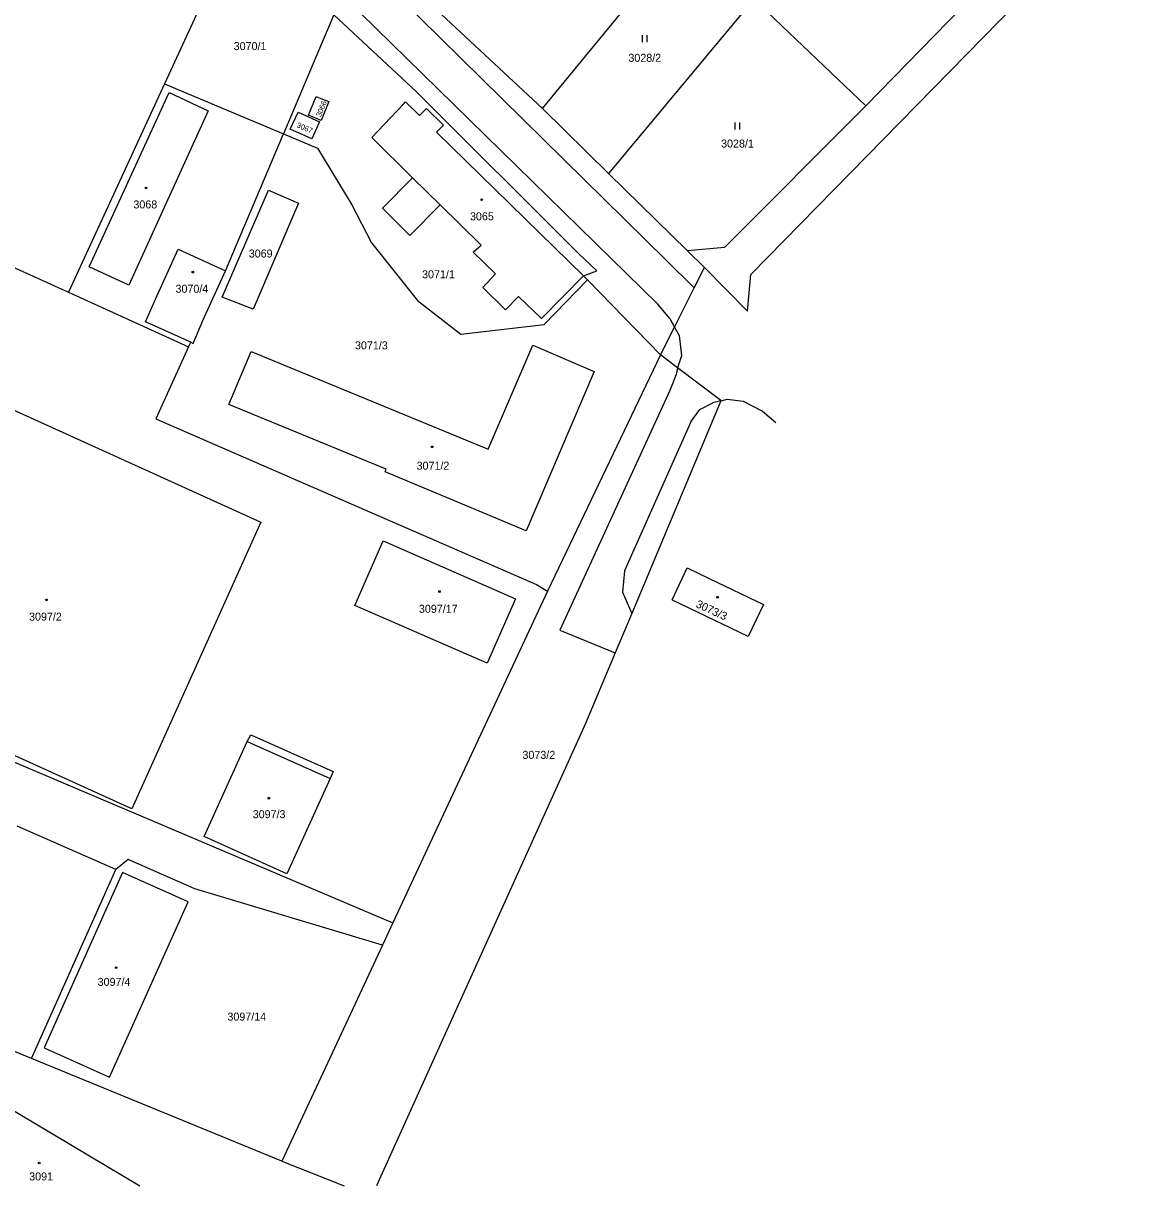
# Model space of a CAD drawing. Extents: x -527335 to -526256, y -1079142 to -1077809.
# Drawn here: x -526618.3 to -526379.4, y -1079141.5 to -1078894.6 of the extents above; entities that cross this region are included whole.
import ezdxf

# ---------------------------------------------------------------- set-up
doc = ezdxf.new("R2010")
doc.units = 0
for name, color, linetype in [('Vrstva 1', 7, 'Continuous'), ('Vrstva 2', 7, 'Continuous'), ('Vrstva 3', 7, 'Continuous'), ('Vrstva 4', 7, 'Continuous'), ('Vrstva 5', 7, 'Continuous')]:
    doc.layers.add(name, color=color, linetype=linetype)

msp = doc.modelspace()

# ---------------------------------------------------------------- linework, layer by layer
at = {"layer": 'Vrstva 1'}
for p, q in [((-526508.07, -1078912.73), (-526477.68, -1078875.63)), ((-526463.23, -1078889.43), (-526494.04, -1078926.52)), ((-526463.23, -1078889.43), (-526439.43, -1078912.18)), ((-526552.41, -1078892.82), (-526555.43, -1078899.96)), ((-526534.91, -1078909.1), (-526552.41, -1078892.82)), ((-526529.63, -1078892.67), (-526508.07, -1078912.73)), ((-526555.43, -1078899.96), (-526563.09, -1078918.07)), ((-526588.32, -1078907.48), (-526608.69, -1078951.75)), ((-526588.32, -1078907.48), (-526563.09, -1078918.07)), ((-526494.04, -1078926.52), (-526508.07, -1078912.73)), ((-526575.39, -1078947.17), (-526563.09, -1078918.07)), ((-526563.09, -1078918.07), (-526555.83, -1078921.12)), ((-526477.29, -1078942.98), (-526494.04, -1078926.52)), ((-526477.29, -1078942.98), (-526473.72, -1078946.48)), ((-526473.72, -1078946.48), (-526464.58, -1078955.73)), ((-526483.04, -1078965.07), (-526498.52, -1078949.13)), ((-526608.69, -1078951.75), (-526583.25, -1078963.33)), ((-526483.04, -1078965.07), (-526507.04, -1079015.24)), ((-526479.44, -1078967.79), (-526483.04, -1078965.07)), ((-526470.21, -1078974.76), (-526479.44, -1078967.79)), ((-526470.15, -1078974.81), (-526470.21, -1078974.76)), ((-526507.04, -1079015.24), (-526539.87, -1079085.69)), ((-526498.95, -1079043.36), (-526542.74, -1079140.28)), ((-526598.64, -1079074.35), (-526619.63, -1079065.16)), ((-526616.56, -1079114.53), (-526598.64, -1079074.35)), ((-526539.87, -1079085.69), (-526542.07, -1079090.41)), ((-526542.07, -1079090.41), (-526563.45, -1079136.3)), ((-526616.56, -1079114.53), (-526662.29, -1079095.78)), ((-526563.45, -1079136.3), (-526616.56, -1079114.53)), ((-526563.45, -1079136.3), (-526550.17, -1079141.53)), ((-526542.74, -1079140.28), (-526543.31, -1079141.53))]:
    msp.add_line(p, q, dxfattribs=at)
for points in [[(-526410.53, -1078846.68), (-526397.22, -1078864.18), (-526401.55, -1078873.2), (-526439.43, -1078912.18)], [(-526464.58, -1078955.73), (-526463.83, -1078947.95), (-526379.39, -1078861.67)], [(-526572.83, -1078873.83), (-526575.65, -1078879.95), (-526588.32, -1078907.48)], [(-526579.03, -1078913.2), (-526595.91, -1078950.25), (-526604.31, -1078946.38), (-526587.37, -1078909.35), (-526579.03, -1078913.2)], [(-526554.76, -1078910.7), (-526553.45, -1078911.2), (-526555.06, -1078915.25), (-526557.74, -1078914.16), (-526556.12, -1078910.18), (-526554.76, -1078910.7)], [(-526499.36, -1078948.26), (-526508.33, -1078957.3), (-526513.2, -1078952.65), (-526515.92, -1078955.46), (-526520.73, -1078950.74), (-526518.09, -1078947.84), (-526522.83, -1078943.22), (-526521.14, -1078941.78), (-526529.82, -1078933.2), (-526536.22, -1078939.7), (-526542.04, -1078933.91), (-526535.66, -1078927.43), (-526544.35, -1078918.84), (-526537.68, -1078911.85), (-526537.18, -1078911.32), (-526534.21, -1078914.22), (-526532.69, -1078912.68), (-526529.11, -1078916.24), (-526530.6, -1078917.74), (-526499.36, -1078948.26)], [(-526498.52, -1078949.13), (-526499.36, -1078948.26), (-526496.56, -1078947.22), (-526500.39, -1078943.58), (-526534.91, -1078909.1)], [(-526561.68, -1078917.14), (-526559.96, -1078913.52), (-526555.39, -1078915.52), (-526557.04, -1078919.16), (-526561.68, -1078917.14)], [(-526439.43, -1078912.18), (-526469.48, -1078942.24), (-526477.29, -1078942.98)], [(-526691.64, -1078914.07), (-526638.3, -1078938.3), (-526619.95, -1078946.64), (-526608.69, -1078951.75)], [(-526555.83, -1078921.12), (-526548.53, -1078933.15), (-526544.38, -1078941.22), (-526534.65, -1078953.51), (-526525.41, -1078960.63), (-526507.76, -1078958.6), (-526498.52, -1078949.13)], [(-526566.28, -1078930.06), (-526559.91, -1078932.85), (-526569.53, -1078955.32), (-526576.11, -1078952.82), (-526566.28, -1078930.06)], [(-526583.25, -1078963.33), (-526582.73, -1078962.38), (-526582.25, -1078962.6), (-526580.18, -1078957.77), (-526575.39, -1078947.17)], [(-526483.04, -1078965.07), (-526480.07, -1078959.14), (-526475.9, -1078950.84), (-526473.72, -1078946.48)], [(-526583.25, -1078963.33), (-526590.15, -1078978.64), (-526509.33, -1079013.84), (-526507.04, -1079015.24)], [(-526541.48, -1078989.9), (-526541.24, -1078989.35), (-526574.66, -1078975.58), (-526569.94, -1078964.3), (-526519.59, -1078985.06), (-526510.15, -1078962.99), (-526497.11, -1078968.56), (-526511.58, -1079002.41), (-526541.48, -1078989.9)], [(-526595.23, -1079061.45), (-526657.34, -1079033.27), (-526629.87, -1078972.47), (-526567.85, -1079000.59), (-526595.23, -1079061.45)], [(-526470.21, -1078974.76), (-526470.24, -1078974.84), (-526489.15, -1079019.96), (-526492.67, -1079028.37), (-526498.95, -1079043.36)], [(-526792.35, -1078978.47), (-526658.25, -1079035.42), (-526539.87, -1079085.69)], [(-526519.83, -1079030.53), (-526547.95, -1079018.26), (-526541.93, -1079004.57), (-526513.85, -1079016.84), (-526519.83, -1079030.53)], [(-526461.14, -1079018.05), (-526464.39, -1079024.87), (-526480.51, -1079017.14), (-526480.59, -1079017.1), (-526477.34, -1079010.26), (-526472.67, -1079012.56), (-526461.14, -1079018.05)], [(-526553.19, -1079055.06), (-526562.38, -1079075.31), (-526579.89, -1079067.37), (-526570.75, -1079047.18), (-526570.02, -1079045.72), (-526552.49, -1079053.53), (-526553.19, -1079055.06)], [(-526542.07, -1079090.41), (-526581.9, -1079078.47), (-526596.06, -1079072.23), (-526598.64, -1079074.35)], [(-526599.97, -1079118.46), (-526583.3, -1079081.2), (-526597.22, -1079074.98), (-526613.89, -1079112.23), (-526599.97, -1079118.46)], [(-526661.2, -1079101.27), (-526659.92, -1079099.09), (-526639.61, -1079110.66), (-526641.13, -1079113.22), (-526593.58, -1079141.53)]]:
    msp.add_lwpolyline(points, dxfattribs=at)
at = {"layer": 'Vrstva 3'}
for p, q in [((-526486.87, -1078898.63), (-526486.87, -1078897.13)), ((-526485.87, -1078898.63), (-526485.87, -1078897.13)), ((-526467.19, -1078917.21), (-526467.19, -1078915.71)), ((-526466.19, -1078917.21), (-526466.19, -1078915.71))]:
    msp.add_line(p, q, dxfattribs=at)
at = {"layer": 'Vrstva 4'}
for p, q in [((-526483.62, -1078954.28), (-526598.1, -1078842.1)), ((-526481.85, -1078944.96), (-526565.2, -1078862.78)), ((-526535.66, -1078927.43), (-526529.82, -1078933.2)), ((-526590.22, -1078953.19), (-526585.42, -1078942.57)), ((-526585.42, -1078942.57), (-526575.39, -1078947.17)), ((-526481.85, -1078944.96), (-526475.9, -1078950.84)), ((-526592.39, -1078958), (-526590.22, -1078953.19)), ((-526481.04, -1078957.33), (-526483.62, -1078954.28)), ((-526582.73, -1078962.38), (-526592.39, -1078958)), ((-526481.04, -1078957.33), (-526480.07, -1078959.14)), ((-526480.07, -1078959.14), (-526479.1, -1078960.94)), ((-526479.1, -1078960.94), (-526478.59, -1078965.24)), ((-526478.59, -1078965.24), (-526479.44, -1078967.79)), ((-526479.44, -1078967.79), (-526479.72, -1078969.22)), ((-526479.72, -1078969.22), (-526481.04, -1078972.63)), ((-526481.04, -1078972.63), (-526504.43, -1079023.55)), ((-526474.7, -1078976.67), (-526471.9, -1078975.25)), ((-526470.24, -1078974.84), (-526471.9, -1078975.25)), ((-526470.15, -1078974.81), (-526470.24, -1078974.84)), ((-526470.15, -1078974.81), (-526468.86, -1078974.49)), ((-526468.86, -1078974.49), (-526465.47, -1078974.88)), ((-526465.47, -1078974.88), (-526461.4, -1078977.04)), ((-526476.58, -1078979.26), (-526474.7, -1078976.67)), ((-526461.4, -1078977.04), (-526458.54, -1078979.43)), ((-526476.58, -1078979.26), (-526490.66, -1079010.95)), ((-526490.66, -1079010.95), (-526491.09, -1079015.48)), ((-526491.09, -1079015.48), (-526489.15, -1079019.96)), ((-526504.43, -1079023.55), (-526492.67, -1079028.37)), ((-526570.75, -1079047.18), (-526553.19, -1079055.06))]:
    msp.add_line(p, q, dxfattribs=at)
at = {"layer": 'Vrstva 5'}
for centre in [(-526592.26, -1078929.6), (-526521.01, -1078932.08), (-526582.32, -1078947.47), (-526531.49, -1078984.58), (-526529.95, -1079015.32), (-526613.39, -1079017.08), (-526470.94, -1079016.53), (-526566.18, -1079059.21), (-526598.59, -1079095.22), (-526614.92, -1079136.71)]:
    msp.add_circle(centre, 0.175, dxfattribs=at)

# ---------------------------------------------------------------- texts
at = {"layer": 'Vrstva 2'}
for s, p in [('3070/1', (-526573.64, -1078900.31)), ('3028/2', (-526489.85, -1078902.8)), ('3028/1', (-526470.17, -1078921.01)), ('3068', (-526594.93, -1078933.94)), ('3065', (-526523.48, -1078936.46)), ('3069', (-526570.44, -1078944.37)), ('3071/1', (-526533.65, -1078948.78)), ('3070/4', (-526585.99, -1078951.85)), ('3071/3', (-526547.89, -1078963.88)), ('3071/2', (-526534.81, -1078989.44)), ('3097/2', (-526617.08, -1079021.5)), ('3097/17', (-526534.32, -1079019.83)), ('3073/2', (-526512.34, -1079050.86)), ('3097/3', (-526569.6, -1079063.46)), ('3097/4', (-526602.52, -1079099.08)), ('3097/14', (-526574.97, -1079106.46)), ('3091', (-526617.05, -1079140.4))]:
    msp.add_text(s, height=1.7, dxfattribs=at).set_placement(p)
for s, height, rotation, p in [('3066', 1.14, 68, (-526555.15, -1078914.61)), ('3067', 1.14, 336, (-526560.38, -1078916.64)), ('3073/3', 1.7, 335, (-526475.69, -1079018.56))]:
    msp.add_text(s, height=height, rotation=rotation, dxfattribs=at).set_placement(p)

doc.saveas('drawing.dxf')
